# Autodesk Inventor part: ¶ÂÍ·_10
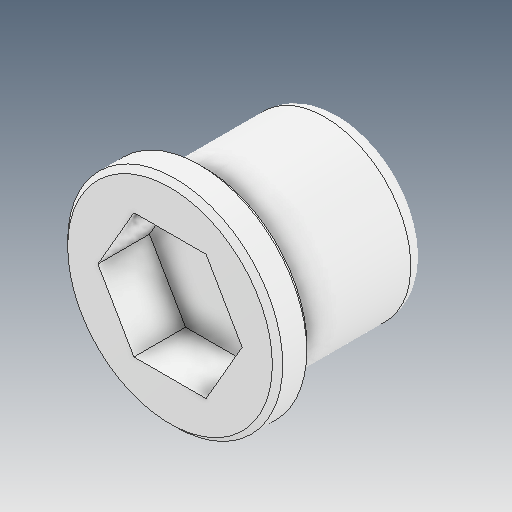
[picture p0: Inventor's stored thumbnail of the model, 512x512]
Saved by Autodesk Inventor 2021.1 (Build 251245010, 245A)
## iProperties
Created: 2021-06
Part Number: ¶ÂÍ·_10
Material: Ogólny
Document SubType Name: Modeling
Designer: user
Density: 1 g/cm^3
Appearance: Domyślna
Author: user
Revision Number: ÈÎºÎ
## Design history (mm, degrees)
feature "ÊäÈë1"
node "Bryła1"
